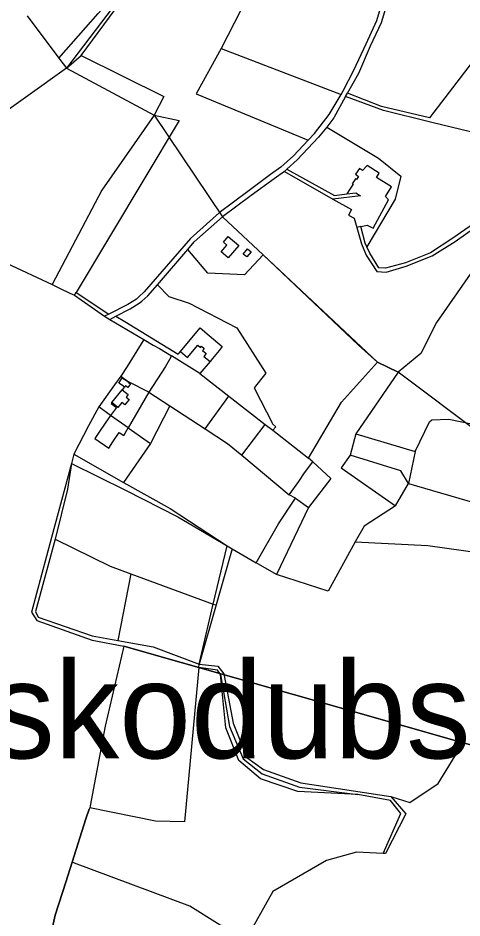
# Model space of a CAD drawing. Extents: x -689422 to -684666, y -987725 to -982160.
# Drawn here: x -688762 to -688371, y -986512 to -985719 of the extents above; entities that cross this region are included whole.
import ezdxf

# ---------------------------------------------------------------- set-up
doc = ezdxf.new("R2010")
doc.units = 0
for name, color, linetype in [('Hranice krajin', 7, 'Continuous'), ('Hranice krajin popis', 7, 'Continuous'), ('Hranice obce', 7, 'Continuous'), ('KN_Hranice_katastrální území', 7, 'Continuous'), ('KN_hranice_parcel', 7, 'Continuous'), ('Krajina lesozemedelska - 3M5', 7, 'Continuous'), ('Krajina lesozemedelska - 5M2', 7, 'Continuous')]:
    doc.layers.add(name, color=color, linetype=linetype)

msp = doc.modelspace()

# ---------------------------------------------------------------- linework, layer by layer
at = {"layer": 'Hranice krajin'}
for points in [[(-688719.74, -985763.51), (-688642.3, -985804.85), (-688582.23, -985894.44)], [(-688317.98, -986557.98), (-688313.41, -986545.52), (-688299.34, -986498.51), (-688290.64, -986463.63), (-688283.74, -986433.83), (-688276.85, -986404.02), (-688270.46, -986381.27), (-688300.76, -986374.22), (-688240.93, -986224.45), (-688244.24, -986223.32), (-688279.78, -986211.22), (-688319.67, -986195.52), (-688310.03, -986161.32), (-688298.64, -986120.9), (-688354.17, -986086.39), (-688427.24, -986031.3), (-688445.57, -986022.52), (-688546.4, -985928.02), (-688582.23, -985894.44)]]:
    msp.add_lwpolyline(points, dxfattribs=at)
at = {"layer": 'Hranice obce'}
for points in [[(-688754.45, -985717.41), (-688726.42, -985754.63), (-688725.62, -985755.69), (-688719.74, -985763.51), (-688753.65, -985787.69), (-688790.22, -985813.59)], [(-688772.43, -985935.24), (-688732.14, -985954.23), (-688725.9, -985957.19), (-688716.62, -985961.59), (-688712.58, -985963.51), (-688686.1, -985982.07), (-688681.44, -985984.82), (-688671.35, -985990.78), (-688651.63, -986002.42), (-688666.1, -986026.28), (-688671.85, -986034.81), (-688677.38, -986042.59), (-688691.03, -986061.81), (-688700.3, -986078.76), (-688713.15, -986103.76), (-688715.28, -986111.7), (-688732.74, -986176.93), (-688750.54, -986242.92), (-688745.87, -986250.12), (-688697.14, -986267.46), (-688669.11, -986272.7), (-688685.65, -986343.35), (-688698.81, -986413.48), (-688699.18, -986415.43), (-688699.56, -986416.51), (-688702.54, -986425.02), (-688714.66, -986463.31), (-688720.16, -986480.67), (-688729.49, -986509.98), (-688735.94, -986537.91)]]:
    msp.add_lwpolyline(points, dxfattribs=at)
at = {"layer": 'KN_Hranice_katastrální území'}
for points in [[(-688754.45, -985717.41), (-688726.42, -985754.63), (-688725.62, -985755.69), (-688719.74, -985763.51), (-688753.65, -985787.69), (-688790.22, -985813.59)], [(-688772.43, -985935.24), (-688732.14, -985954.23), (-688725.9, -985957.19), (-688716.62, -985961.59), (-688712.58, -985963.51), (-688686.1, -985982.07), (-688681.44, -985984.82), (-688671.35, -985990.78), (-688651.63, -986002.42), (-688666.1, -986026.28), (-688671.85, -986034.81), (-688677.38, -986042.59), (-688691.03, -986061.81), (-688700.3, -986078.76), (-688713.15, -986103.76), (-688715.28, -986111.7), (-688732.74, -986176.93), (-688750.54, -986242.92), (-688745.87, -986250.12), (-688697.14, -986267.46), (-688669.11, -986272.7), (-688685.65, -986343.35), (-688698.81, -986413.48), (-688699.18, -986415.43), (-688699.56, -986416.51), (-688702.54, -986425.02), (-688714.66, -986463.31), (-688720.16, -986480.67), (-688729.49, -986509.98), (-688735.94, -986537.91)]]:
    msp.add_lwpolyline(points, dxfattribs=at)
at = {"layer": 'KN_hranice_parcel'}
for p, q in [((-688706.72, -985752.18), (-688671.74, -985704.92)), ((-688446.13, -985721.42), (-688441.42, -985705.62)), ((-688565.72, -985711.78), (-688583.38, -985745.99)), ((-688754.45, -985717.41), (-688726.42, -985754.63)), ((-688583.38, -985745.99), (-688477.72, -985786.71)), ((-688726.42, -985754.63), (-688725.62, -985755.69)), ((-688719.74, -985763.51), (-688706.72, -985752.18)), ((-688725.62, -985755.69), (-688719.74, -985763.51)), ((-688719.74, -985763.51), (-688642.3, -985804.85)), ((-688488.04, -985804.39), (-688477.72, -985786.71)), ((-688477.72, -985786.71), (-688475.82, -985783.45)), ((-688473.62, -985788.31), (-688472.12, -985785.41)), ((-688501.2, -985820.99), (-688488.04, -985804.39)), ((-688506.69, -985826.86), (-688501.2, -985820.99)), ((-688506.69, -985826.86), (-688519.62, -985840.68)), ((-688516.39, -985844.33), (-688525.35, -985852.42)), ((-688525.35, -985852.42), (-688527.66, -985854.5)), ((-688527.66, -985854.5), (-688484.9, -985878.74)), ((-688470.03, -985870.13), (-688472.54, -985874.33)), ((-688472.54, -985874.33), (-688464.71, -985873.42)), ((-688464.71, -985873.42), (-688462.36, -985874.88)), ((-688484.9, -985878.74), (-688468.39, -985888.1)), ((-688582.23, -985894.44), (-688546.4, -985928.02)), ((-688466.24, -985895.62), (-688463.91, -985903.74)), ((-688460.26, -985902.98), (-688463.91, -985903.74)), ((-688463.91, -985903.74), (-688459.76, -985918.18)), ((-688452.36, -985926.54), (-688454.86, -985920.93)), ((-688639.44, -985954.31), (-688612.85, -985923.16)), ((-688732.14, -985954.23), (-688725.9, -985957.19)), ((-688725.9, -985957.19), (-688716.62, -985961.59)), ((-688712.58, -985963.51), (-688711.19, -985961.22)), ((-688711.19, -985961.22), (-688682.48, -985980.26)), ((-688647.83, -985964.13), (-688639.44, -985954.31)), ((-688716.62, -985961.59), (-688712.58, -985963.51)), ((-688712.58, -985963.51), (-688686.1, -985982.07)), ((-688665.66, -985971.85), (-688682.48, -985980.26)), ((-688682.48, -985980.26), (-688686.1, -985982.07)), ((-688686.1, -985982.07), (-688681.44, -985984.82)), ((-688681.44, -985984.82), (-688676.04, -985982.04)), ((-688602.06, -986032.53), (-688627.06, -986017.03)), ((-688593.06, -986021.97), (-688602.06, -986032.53)), ((-688445.57, -986022.52), (-688427.24, -986031.3)), ((-688602.06, -986032.53), (-688576.58, -986052.36)), ((-688427.24, -986031.3), (-688464.77, -986085.7)), ((-688671.85, -986034.81), (-688677.38, -986042.59)), ((-688671.85, -986034.81), (-688664.93, -986039.83)), ((-688664.93, -986039.83), (-688665.27, -986040.25)), ((-688647.12, -986049.07), (-688664.93, -986039.83)), ((-688677.38, -986042.59), (-688691.03, -986061.81)), ((-688679.72, -986058.1), (-688670.58, -986046.81)), ((-688668.51, -986044.25), (-688670.58, -986046.81)), ((-688647.12, -986049.07), (-688665.31, -986080.44)), ((-688647.12, -986049.07), (-688628.66, -986061.01)), ((-688597.41, -986081.31), (-688576.58, -986052.36)), ((-688576.58, -986052.36), (-688544.45, -986077.37)), ((-688680.84, -986069.63), (-688691.03, -986061.81)), ((-688628.66, -986061.01), (-688645.69, -986094.1)), ((-688628.66, -986061.01), (-688597.41, -986081.31)), ((-688665.31, -986080.44), (-688680.84, -986069.63)), ((-688565.04, -986104.4), (-688544.45, -986077.37)), ((-688544.45, -986077.37), (-688537.73, -986082.6)), ((-688678.69, -986092.82), (-688673.15, -986084.44)), ((-688665.31, -986080.44), (-688645.69, -986094.1)), ((-688537.73, -986082.6), (-688506.34, -986107.03)), ((-688464.77, -986085.7), (-688469.54, -986104.54)), ((-688464.77, -986085.7), (-688412.24, -986101.27)), ((-688645.69, -986094.1), (-688669.34, -986128.45)), ((-688713.15, -986103.76), (-688715.28, -986111.7)), ((-688713.15, -986103.76), (-688669.34, -986128.45)), ((-688412.24, -986101.27), (-688418.13, -986129.42)), ((-688715.28, -986111.7), (-688732.74, -986176.93)), ((-688565.04, -986104.4), (-688523.53, -986139.42)), ((-688502.53, -986110.48), (-688506.34, -986107.03)), ((-688429.62, -986149.12), (-688418.13, -986129.42)), ((-688418.13, -986129.42), (-688310.03, -986161.32)), ((-688517.75, -986142.5), (-688523.53, -986139.42)), ((-688517.75, -986142.5), (-688506.29, -986150.65)), ((-688506.29, -986150.65), (-688534.6, -986209.52)), ((-688732.74, -986176.93), (-688750.54, -986242.92)), ((-688729.63, -986178.55), (-688681.11, -986202.3)), ((-688590.51, -986235.87), (-688578.03, -986184.37)), ((-688573.76, -986187.16), (-688587.72, -986236.43)), ((-688578.03, -986184.37), (-688573.76, -986187.16)), ((-688573.76, -986187.16), (-688552.37, -986199.48)), ((-688681.11, -986202.3), (-688662.86, -986209.06)), ((-688534.6, -986209.52), (-688552.37, -986199.48)), ((-688662.86, -986209.06), (-688674.53, -986267.93)), ((-688662.86, -986209.06), (-688590.51, -986235.87)), ((-688602.73, -986288.72), (-688590.51, -986235.87)), ((-688587.72, -986236.43), (-688602.73, -986288.72)), ((-688590.51, -986235.87), (-688587.72, -986236.43)), ((-688750.54, -986242.92), (-688745.87, -986250.12)), ((-688603.03, -986291.71), (-688602.73, -986288.72)), ((-688685.65, -986343.35), (-688698.81, -986413.48)), ((-688702.54, -986425.02), (-688699.56, -986416.51)), ((-688699.18, -986415.43), (-688699.56, -986416.51)), ((-688698.81, -986413.48), (-688699.18, -986415.43)), ((-688714.66, -986463.31), (-688702.54, -986425.02))]:
    msp.add_line(p, q, dxfattribs=at)
for points in [[(-688726.42, -985754.63), (-688691.8, -985715.16), (-688675.18, -985696.61), (-688664.2, -985686), (-688656.73, -985680.39), (-688654.6, -985675.14)], [(-688657.73, -985685.42), (-688673.71, -985703.04), (-688719.74, -985763.51)], [(-688472.12, -985785.41), (-688462.05, -985767.77), (-688451.8, -985743.82), (-688442.16, -985723.05), (-688432.27, -985690.98)], [(-688475.82, -985783.45), (-688466.33, -985765.2), (-688455.67, -985742.06), (-688446.13, -985721.42)], [(-688342.3, -985732.35), (-688362.2, -985758.08), (-688399.76, -985807.16), (-688442.07, -985797.21), (-688472.12, -985785.41)], [(-688583.38, -985745.99), (-688605.33, -985786.18), (-688506.69, -985826.86)], [(-688706.72, -985752.18), (-688633.8, -985788.45), (-688642.3, -985804.85)], [(-688719.74, -985763.51), (-688753.65, -985787.69), (-688790.22, -985813.59), (-688803.29, -985826.72), (-688819.38, -985853.06), (-688826.87, -985863.54)], [(-688473.62, -985788.31), (-688484.06, -985807.28), (-688490.22, -985815.56)], [(-688287.53, -985836.47), (-688322.34, -985831.23), (-688363.66, -985819.67), (-688397.69, -985811.28), (-688440.36, -985800.72), (-688473.62, -985788.31)], [(-688642.3, -985804.85), (-688688.58, -985870.89), (-688732.14, -985954.23)], [(-688642.3, -985804.85), (-688620.38, -985809.69), (-688711.19, -985961.22)], [(-688490.22, -985815.56), (-688497.56, -985824.31), (-688516.39, -985844.33)], [(-688490.22, -985815.56), (-688444.67, -985842.74), (-688424.97, -985858.52), (-688430.05, -985878.77), (-688454.86, -985920.93)], [(-688519.62, -985840.68), (-688530.64, -985850.74), (-688539.96, -985857.13), (-688559.94, -985872.04), (-688585.05, -985891.01), (-688610.44, -985913.66), (-688651.17, -985960.51), (-688656.07, -985965.37), (-688658.08, -985966.93), (-688665.66, -985971.85)], [(-688446.58, -985859.87), (-688444.18, -985855.98), (-688454.52, -985849.29), (-688458.74, -985853.75)], [(-688527.66, -985854.5), (-688536.65, -985861.08), (-688556.78, -985875.72), (-688582.23, -985894.44)], [(-688525.35, -985852.42), (-688483.39, -985875.59), (-688472.54, -985874.33)], [(-688458.74, -985853.75), (-688461.46, -985851.92), (-688465.06, -985856.94), (-688462.39, -985858.85), (-688464.18, -985861.58), (-688464.9, -985861.11), (-688467.78, -985865.32), (-688467.07, -985865.81), (-688470.03, -985870.13)], [(-688438.56, -985876.65), (-688433.25, -985868.09), (-688446.58, -985859.87)], [(-688462.36, -985874.88), (-688460.55, -985875.98), (-688484.9, -985878.74)], [(-688460.26, -985902.98), (-688454.77, -985901.83), (-688449.35, -985904.58), (-688435.88, -985879.34), (-688438.56, -985876.65)], [(-688323.9, -985881.67), (-688357.09, -985935.41), (-688393.46, -985987.7), (-688407.45, -986014.99), (-688427.24, -986031.3)], [(-688468.39, -985888.1), (-688471.06, -985892.99), (-688466.24, -985895.62)], [(-688459.76, -985918.18), (-688455.47, -985928.2), (-688446.22, -985942.5), (-688437.79, -985943.18), (-688420.22, -985937.98), (-688397.44, -985928.96), (-688377.15, -985916.09), (-688356.89, -985901.91), (-688331.42, -985885.43)], [(-688332.83, -985882.77), (-688358.04, -985898.57), (-688379.05, -985913.34), (-688398.75, -985926.18), (-688421.02, -985935.03), (-688438.36, -985939.77), (-688444.4, -985939.51), (-688452.36, -985926.54)], [(-688612.85, -985923.16), (-688607.12, -985916.45), (-688582.23, -985894.44)], [(-688454.86, -985920.93), (-688456.32, -985917.65), (-688460.26, -985902.98)], [(-688567.85, -985919.61), (-688577.11, -985930.55), (-688583.48, -985925.17), (-688578.48, -985919.28), (-688581.39, -985916.8), (-688577.11, -985911.76), (-688567.85, -985919.61)], [(-688800.67, -985917.17), (-688772.43, -985935.24), (-688732.14, -985954.23)], [(-688546.4, -985928.02), (-688562.72, -985945.7), (-688595.12, -985944.03), (-688612.85, -985923.16)], [(-688559.99, -985922.65), (-688556.96, -985925.22), (-688560.83, -985929.82), (-688563.91, -985927.21), (-688559.99, -985922.65)], [(-688546.4, -985928.02), (-688462.38, -986007.69), (-688445.57, -986022.52)], [(-688639.44, -985954.31), (-688629.56, -985964.66), (-688611.45, -985970.61), (-688569.64, -985992.28), (-688544.08, -986032.11), (-688554.36, -986045.3), (-688537.94, -986077.22), (-688535.21, -986079.63), (-688537.73, -986082.6)], [(-688676.04, -985982.04), (-688663.51, -985975.6), (-688655.5, -985970.51), (-688653.28, -985968.7), (-688647.83, -985964.13)], [(-688681.44, -985984.82), (-688671.35, -985990.78), (-688651.63, -986002.42)], [(-688676.04, -985982.04), (-688668.28, -985986.78), (-688621.27, -986015.48), (-688619.22, -986013.12)], [(-688619.22, -986013.12), (-688601.91, -985992.28), (-688593.98, -985998.97), (-688582.31, -986008.82), (-688585.22, -986012.38), (-688590.96, -986019.4), (-688593.06, -986021.97)], [(-688651.63, -986002.42), (-688666.1, -986026.28), (-688671.85, -986034.81)], [(-688651.63, -986002.42), (-688643.27, -986007.62), (-688637.6, -986010.49), (-688627.06, -986017.03)], [(-688619.22, -986013.12), (-688612.87, -986018.33), (-688603.9, -986007.65), (-688601.55, -986009.58), (-688600.63, -986008.46), (-688598.24, -986010.42), (-688599.71, -986012.21), (-688596.49, -986014.88), (-688598.59, -986017.45), (-688593.06, -986021.97)], [(-688627.06, -986017.03), (-688628.88, -986020.29), (-688632.29, -986026.4), (-688647.12, -986049.07)], [(-688506.34, -986107.03), (-688477.14, -986057.8), (-688445.57, -986022.52)], [(-688668.51, -986044.25), (-688673.54, -986040.93), (-688670.5, -986036.33), (-688665.12, -986039.87), (-688665.27, -986040.25)], [(-688665.27, -986040.25), (-688663.29, -986041.56), (-688665.46, -986044.85), (-688667.51, -986043.5), (-688668.16, -986044.48), (-688668.51, -986044.25)], [(-688670.58, -986046.81), (-688665.23, -986051.13), (-688667.05, -986053.39), (-688664.49, -986055.51), (-688668.36, -986060.28), (-688670.91, -986058.19), (-688674.32, -986062.43), (-688679.72, -986058.1)], [(-688691.03, -986061.81), (-688700.3, -986078.76), (-688713.15, -986103.76)], [(-688679.72, -986058.1), (-688680.37, -986058.91), (-688675.59, -986062.57), (-688680.84, -986069.63)], [(-688680.84, -986069.63), (-688685.69, -986076.16), (-688691.22, -986084.52)], [(-688412.24, -986101.27), (-688399.6, -986075.08), (-688397.63, -986073.33), (-688382.65, -986072.65), (-688354.12, -986078.58)], [(-688691.22, -986084.52), (-688694.81, -986089.95), (-688682.35, -986098.36), (-688678.69, -986092.82)], [(-688673.15, -986084.44), (-688669.16, -986087.07), (-688665.31, -986080.44)], [(-688597.41, -986081.31), (-688577.78, -986094.17), (-688565.04, -986104.4)], [(-688715.28, -986111.7), (-688718.63, -986134.56), (-688729.63, -986178.55)], [(-688715.28, -986111.7), (-688667.52, -986135.24), (-688621.45, -986158.8), (-688578.03, -986184.37)], [(-688523.53, -986139.42), (-688515.01, -986127.56), (-688509.78, -986120.1), (-688502.53, -986110.48)], [(-688502.53, -986110.48), (-688486.68, -986125.03), (-688506.29, -986150.65)], [(-688469.54, -986104.54), (-688477.68, -986115.66), (-688429.62, -986149.12)], [(-688418.13, -986129.42), (-688424.9, -986118.43), (-688469.54, -986104.54)], [(-688669.34, -986128.45), (-688628.23, -986151.62), (-688578.03, -986184.37)], [(-688552.37, -986199.48), (-688532.88, -986164.9), (-688517.75, -986142.5)], [(-688429.62, -986149.12), (-688457.24, -986167.09), (-688465.19, -986180.81)], [(-688729.63, -986178.55), (-688746.9, -986242.27), (-688744.47, -986247.13), (-688697.05, -986263.72), (-688674.53, -986267.93)], [(-688465.19, -986180.81), (-688488.89, -986224.22), (-688534.6, -986209.52)], [(-688465.19, -986180.81), (-688401.09, -986184.22), (-688319.67, -986195.52)], [(-688745.87, -986250.12), (-688697.14, -986267.46), (-688669.11, -986272.7), (-688685.65, -986343.35)], [(-688674.53, -986267.93), (-688643.17, -986273.5), (-688602.73, -986288.72)], [(-688603.03, -986291.71), (-688615.78, -986427.72), (-688641.13, -986426.91), (-688699.18, -986415.43)], [(-688583.99, -986297.77), (-688586.55, -986293.85), (-688603.03, -986291.71)], [(-688602.73, -986288.72), (-688586.2, -986290.37), (-688581.04, -986297.2), (-688572.67, -986340.68), (-688560.75, -986370.97), (-688545.9, -986381.62), (-688513, -986393.32), (-688433.71, -986405.4)], [(-688583.99, -986297.77), (-688575.96, -986343.59), (-688564.01, -986372.25), (-688547.24, -986385.39), (-688514.34, -986397.09), (-688462.76, -986403.5)], [(-688462.76, -986403.5), (-688515.68, -986400.86), (-688548.75, -986389.63), (-688567.73, -986373.72), (-688579.19, -986344.94), (-688583.99, -986297.77)], [(-688433.71, -986405.4), (-688417.16, -986410.57), (-688392.14, -986393.72), (-688370.08, -986357.88), (-688305.26, -986373.78)], [(-688440.57, -986455.42), (-688425.03, -986420.17), (-688434.24, -986408.86), (-688462.76, -986403.5)], [(-688433.71, -986405.4), (-688420.69, -986420.47), (-688438.57, -986455.5), (-688440.57, -986455.42)], [(-688440.57, -986455.42), (-688464.06, -986454.46), (-688490.47, -986461.68), (-688537.78, -986489.13), (-688562.11, -986532.46), (-688610.93, -986501.88), (-688712.6, -986464.08), (-688714.66, -986463.31)], [(-688745.64, -986569.21), (-688735.94, -986537.91), (-688729.49, -986509.98), (-688720.16, -986480.67), (-688714.66, -986463.31)]]:
    msp.add_lwpolyline(points, dxfattribs=at)
at = {"layer": 'Krajina lesozemedelska - 3M5'}
for points in [[(-688669.11, -986272.7), (-688685.65, -986343.35), (-688698.81, -986413.48), (-688699.18, -986415.43), (-688699.56, -986416.51), (-688702.54, -986425.02), (-688714.66, -986463.31), (-688720.16, -986480.67), (-688729.49, -986509.98), (-688735.94, -986537.91), (-688745.64, -986569.21), (-688736.48, -986573.33), (-688622, -986603.98), (-688614.63, -986626.48), (-688547.16, -986661.81), (-688502.75, -986692.68), (-688511.14, -986710.83), (-688455.25, -986756.85), (-688406.43, -986788.29), (-688396.34, -986794.79), (-688378.96, -986803.58)], [(-688275.55, -986383.2), (-688370.08, -986357.88), (-688669.11, -986272.7)]]:
    msp.add_lwpolyline(points, dxfattribs=at)
at = {"layer": 'Krajina lesozemedelska - 5M2'}
for points in [[(-688754.45, -985717.41), (-688726.42, -985754.63), (-688725.62, -985755.69), (-688719.74, -985763.51), (-688753.65, -985787.69), (-688790.22, -985813.59)], [(-688772.43, -985935.24), (-688732.14, -985954.23), (-688725.9, -985957.19), (-688716.62, -985961.59), (-688712.58, -985963.51), (-688686.1, -985982.07), (-688681.44, -985984.82), (-688671.35, -985990.78), (-688651.63, -986002.42), (-688666.1, -986026.28), (-688671.85, -986034.81), (-688677.38, -986042.59), (-688691.03, -986061.81), (-688700.3, -986078.76), (-688713.15, -986103.76), (-688715.28, -986111.7), (-688732.74, -986176.93), (-688750.54, -986242.92), (-688745.87, -986250.12), (-688697.14, -986267.46), (-688669.11, -986272.7)], [(-688669.11, -986272.7), (-688370.08, -986357.88), (-688275.55, -986383.2), (-688083.69, -986418.21), (-687888.75, -986572.55), (-687722.74, -986669.66), (-687622, -986726.45), (-687591.3, -986741.74), (-687484.29, -986822.08), (-687338.92, -986962.93), (-687137.9, -987140.22), (-686763.85, -987188.16)]]:
    msp.add_lwpolyline(points, dxfattribs=at)

# ---------------------------------------------------------------- texts
at = {"layer": 'Hranice krajin popis'}
msp.add_text('10-1 Českodubsko', height=85, dxfattribs=at).set_placement((-689191.21, -986371.64))

doc.saveas('drawing.dxf')
